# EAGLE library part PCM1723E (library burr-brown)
SoundPlus(TM) Stereo Audio DAC with Programmable PLL
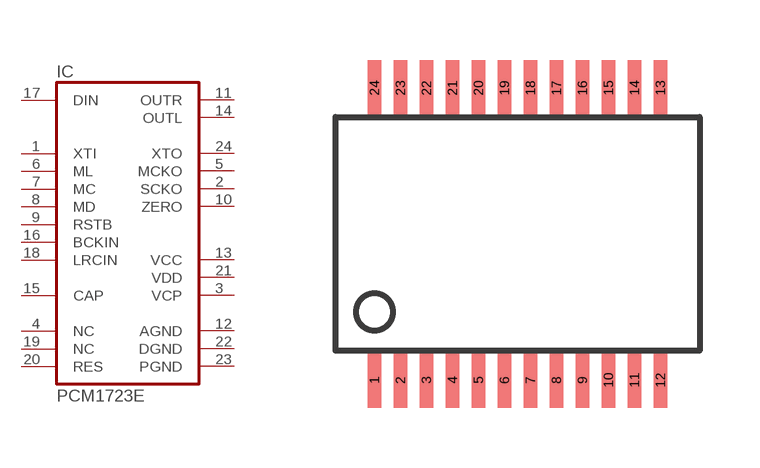
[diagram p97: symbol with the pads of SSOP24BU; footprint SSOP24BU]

Designator prefix IC

## PCM1723E (MPN: PCM1723EG4; OC_FARNELL: 1234896; OC_NEWARK: 66K4046)  [SSOP24BU]
1  XTI  in
2  SCKO  out
3  VCP  pwr
4  NC  nc
5  MCKO  out
6  ML  in
7  MC  in
8  MD  in
9  RSTB  in
10  ZERO  out
11  OUTR  out
12  AGND  pwr
13  VCC  pwr
14  OUTL  out
15  CAP  pas
16  BCKIN  in
17  DIN  in
18  LRCIN  in
19  NC  nc
20  RES  pas
21  VDD  pwr
22  DGND  pwr
23  PGND  pwr
24  XTO  out

## Footprint SSOP24BU (pad centres in mm)
Small Shrink Outline Package
smd 0.348 x 1.397: 1 -3.575,-3.656; 2 -2.925,-3.656; 3 -2.275,-3.656; 4 -1.625,-3.656; 5 -0.975,-3.656; 6 -0.325,-3.656; 7 0.325,-3.656; 8 0.975,-3.656; 9 1.625,-3.656; 10 2.275,-3.656; 11 2.925,-3.656; 12 3.575,-3.656; 13 3.575,3.656; 14 2.925,3.656; 15 2.275,3.656; 16 1.625,3.656; 17 0.975,3.656; 18 0.325,3.656; 19 -0.325,3.656; 20 -0.975,3.656; 21 -1.625,3.656; 22 -2.275,3.656; 23 -2.925,3.656; 24 -3.575,3.656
